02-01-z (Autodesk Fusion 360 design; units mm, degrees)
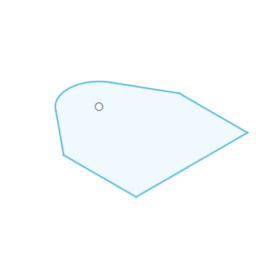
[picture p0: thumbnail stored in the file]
sketch "スケッチ" plane through (0, 0, 0) normal (0, 1, 0) x axis (1, 0, 0)
  line L1 (-4.2557, 35.2477) -> (-30.8824, 20.0622)
  line L2 (37.3484, 35.2477) -> (-4.2557, 35.2477)
  line L3 (37.3484, -32.5669) -> (37.3484, 35.2477)
  line L4 (-6.752, -32.5669) -> (37.3484, -32.5669)
  line L5 (-32.5465, -11.5569) -> (-6.752, -32.5669)
  arc A1 centre (-21.5612, 3.7183) radius 18.8151 clockwise from (-32.5465, -11.5569) to (-30.8824, 20.0622)
  horizontal L2
  perpendicular L2 L3
  perpendicular L3 L4
  tangent L1 A1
